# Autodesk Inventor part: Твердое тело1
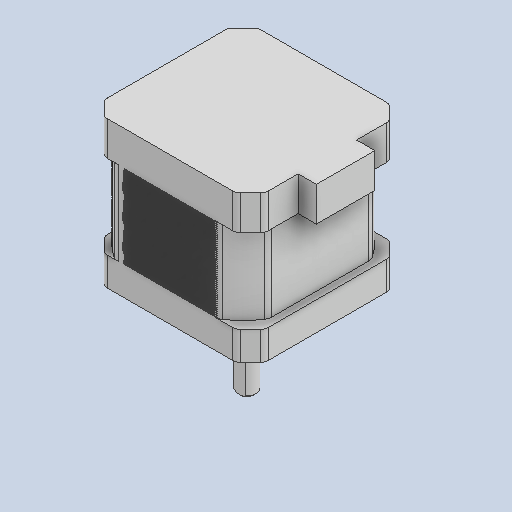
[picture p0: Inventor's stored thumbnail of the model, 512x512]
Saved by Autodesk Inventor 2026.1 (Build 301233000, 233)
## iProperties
Created: 2026-01
Part Number: Твердое тело1
Material: Типовые
Document SubType Name: Modeling
Designer: Yury Melnikov
Density: 1 g/cm^3
Appearance: По умолчанию
Author: Yury Melnikov
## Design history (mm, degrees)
derived "Nema17H44.ipt"
feature "Твердое тело1::Nema17H44.ipt" dims "d0" = 10
tag "Элемент создания тегов1"
node "Твердое тело1"
